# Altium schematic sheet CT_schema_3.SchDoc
size 313 x 200 mm
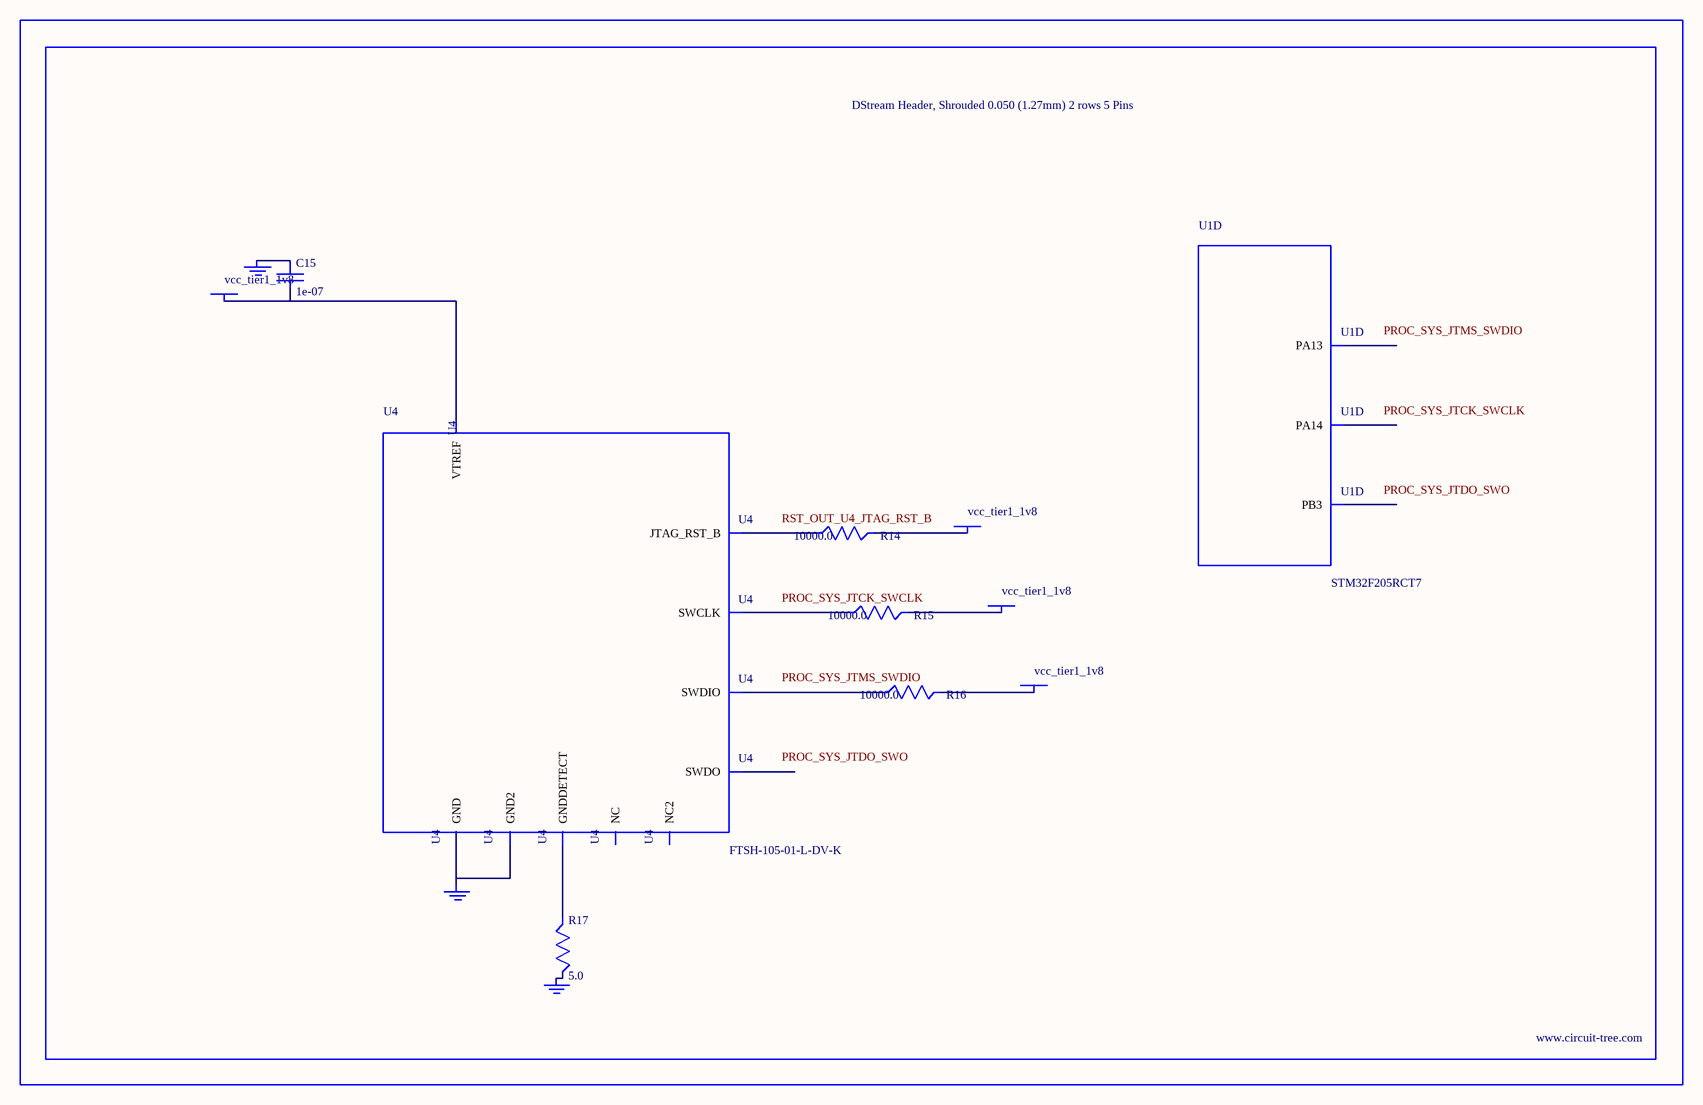
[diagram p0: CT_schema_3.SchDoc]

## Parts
BORDER2  (no value)
C15  1e-07  [C0402]
GND_INSTANCE_2_0  (no value)
GND_INSTANCE_2_1  (no value)
GND_INSTANCE_2_2  (no value)
POWER_INSTANCE_2_0  vcc_tier1_1v8
POWER_INSTANCE_2_1  vcc_tier1_1v8
POWER_INSTANCE_2_2  vcc_tier1_1v8
POWER_INSTANCE_2_3  vcc_tier1_1v8
R14  10000.0  [R0603]
R15  10000.0  [R0603]
R16  10000.0  [R0603]
R17  5.0  [R0603]
U1  STM32F205RCT7  [LQFP64]  (part D of 7)
U4  FTSH-105-01-L-DV-K  [SAMTEC_FTSH-105-01-L-DV-K]

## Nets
NetC15_1: C15.1 GND_INSTANCE_2_0.0(GND)
NetC15_2: C15.2 POWER_INSTANCE_2_0.0(PWR) U4.1(VTREF)
NetGND_INSTANCE_2_1_0: GND_INSTANCE_2_1.0(GND) R17.2
NetGND_INSTANCE_2_2_0: GND_INSTANCE_2_2.0(GND) U4.3(GND) U4.5(GND2)
NetPOWER_INSTANCE_2_1_0: POWER_INSTANCE_2_1.0(PWR) R16.2
NetPOWER_INSTANCE_2_2_0: POWER_INSTANCE_2_2.0(PWR) R15.2
NetPOWER_INSTANCE_2_3_0: POWER_INSTANCE_2_3.0(PWR) R14.2
NetR14_1: R14.1 U4.10(JTAG_RST_B)
NetR15_1: R15.1 U4.4(SWCLK)
NetR16_1: R16.1 U4.2(SWDIO)
NetR17_1: R17.1 U4.9(GNDDETECT)

Not connected (* = marked no-connect by the designer): U1 46(PA13) 49(PA14) 55(PB3); U4 6(SWDO) 7(NC) 8(NC2)

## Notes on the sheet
- Labels drawn without touching a wire or pin: PROC_SYS_JTCK_SWCLK, PROC_SYS_JTDO_SWO, PROC_SYS_JTMS_SWDIO, RST_OUT_U4_JTAG_RST_B

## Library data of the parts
BORDER2 = BORDER_PAGE2
C15 = C0402C104K3RACTU
GND_INSTANCE_2_0-GND_INSTANCE_2_2 = GND
POWER_INSTANCE_2_0-POWER_INSTANCE_2_3 = PWR
R14-R16 = RC0603JR-0710KL
R17 = ERJ-3GEYJ5R1V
